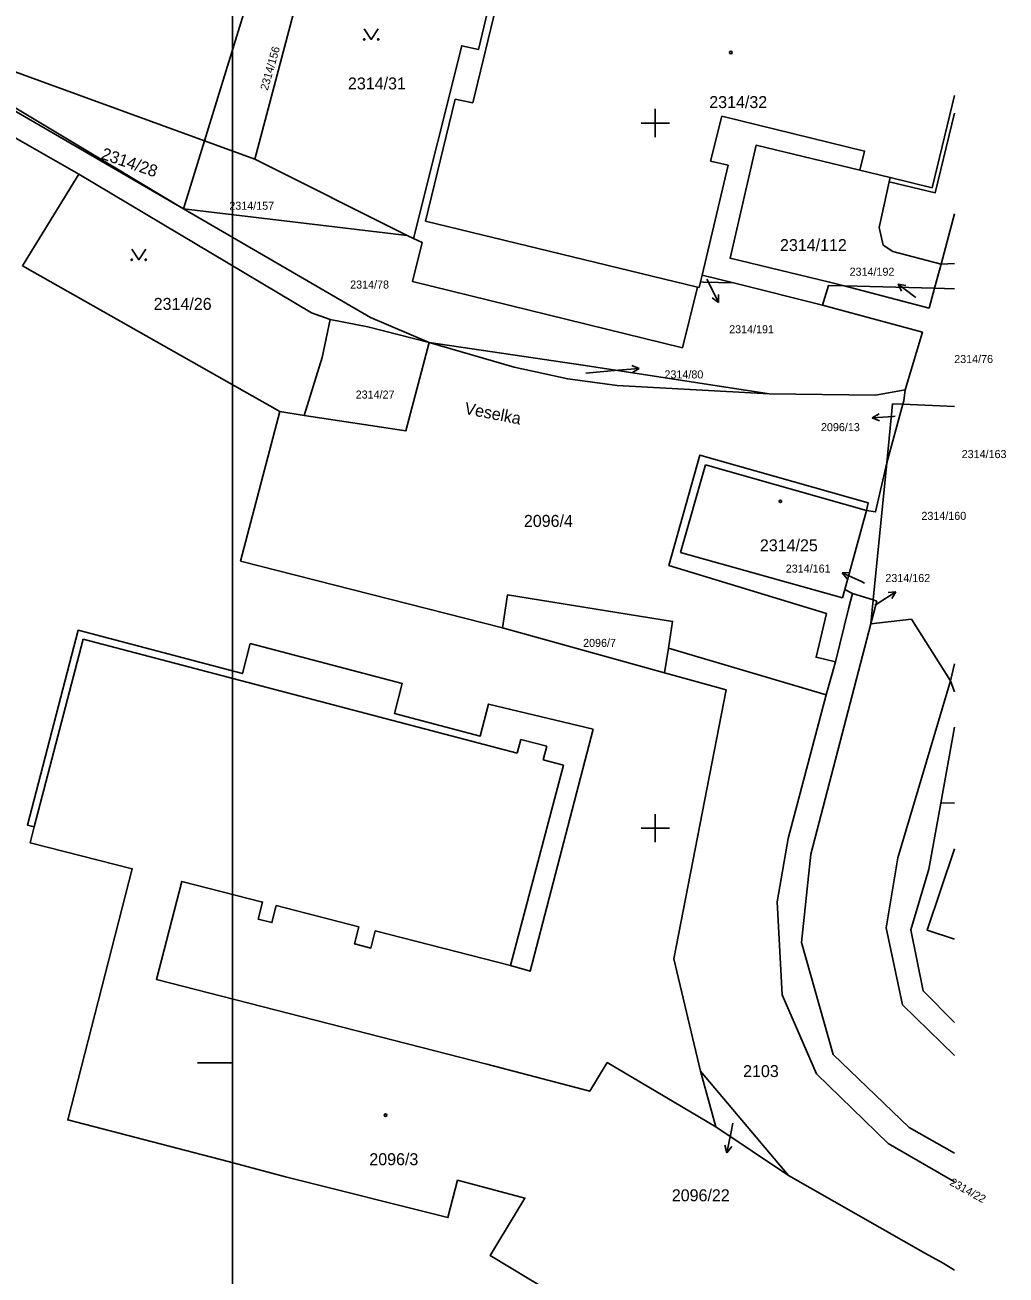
# Model space of a CAD drawing. Extents: x -599970 to -599524, y -1154772 to -1154457.
# Drawn here: x -599594.7 to -599525.1, y -1154681.7 to -1154593 of the extents above; entities that cross this region are included whole.
import ezdxf

# ---------------------------------------------------------------- set-up
doc = ezdxf.new("R2010")
doc.units = 0
for name, color, linetype in [('Z-KATASTRALNI MAPA', 7, 'Continuous'), ('Z-KRIZKY CTVERCOVE SITE', 7, 'Continuous'), ('Z-RAM ROZPISKA', 7, 'Continuous')]:
    doc.layers.add(name, color=color, linetype=linetype)

msp = doc.modelspace()

# ---------------------------------------------------------------- linework, layer by layer
at = {"layer": 'Z-KATASTRALNI MAPA'}
for p, q in [((-599562.95, -1154598.56), (-599560.21, -1154587.23)), ((-599581.98, -1154601.27), (-599578.2, -1154588.98)), ((-599575.02, -1154589.76), (-599578.41, -1154602.57)), ((-599581.98, -1154601.27), (-599603.91, -1154593.29)), ((-599590.89, -1154603.63), (-599607.38, -1154594.23)), ((-599528.77, -1154598.05), (-599530.36, -1154604.59)), ((-599566.31, -1154606.95), (-599564.2, -1154598.31)), ((-599564.2, -1154598.31), (-599562.95, -1154598.56)), ((-599546.08, -1154602.7), (-599545.28, -1154599.52)), ((-599583.46, -1154606.09), (-599581.98, -1154601.27)), ((-599581.98, -1154601.27), (-599578.41, -1154602.57)), ((-599578.41, -1154602.57), (-599567.6, -1154607.98)), ((-599544.84, -1154602.99), (-599546.08, -1154602.7)), ((-599546.68, -1154610.8), (-599544.84, -1154602.99)), ((-599590.89, -1154603.63), (-599594.88, -1154610.13)), ((-599574.38, -1154613.45), (-599590.89, -1154603.63)), ((-599530.36, -1154604.59), (-599533.33, -1154603.87)), ((-599567.6, -1154607.98), (-599583.46, -1154606.09)), ((-599566.31, -1154606.95), (-599547.01, -1154611.63)), ((-599567.6, -1154607.98), (-599567.16, -1154608.2)), ((-599576.64, -1154620.46), (-599594.88, -1154610.13)), ((-599529.73, -1154610.01), (-599530.19, -1154611.71)), ((-599546.34, -1154611.07), (-599546.18, -1154611.38)), ((-599546.18, -1154611.38), (-599545.522, -1154612.728)), ((-599544.46, -1154611.34), (-599538.14, -1154612.91)), ((-599536.61, -1154611.55), (-599530.19, -1154611.71)), ((-599531.58, -1154612.33), (-599532.779, -1154611.427)), ((-599532.779, -1154611.427), (-599532.228, -1154611.529)), ((-599532.779, -1154611.427), (-599532.529, -1154611.928)), ((-599545.522, -1154612.728), (-599545.967, -1154612.389)), ((-599545.522, -1154612.728), (-599545.517, -1154612.169)), ((-599531.52, -1154612.38), (-599531.58, -1154612.33)), ((-599528.77, -1154611.75), (-599530.19, -1154611.71)), ((-599573.07, -1154613.94), (-599574.38, -1154613.45)), ((-599554.92, -1154617.74), (-599552.63, -1154617.53)), ((-599552.63, -1154617.53), (-599551.135, -1154617.399)), ((-599551.135, -1154617.399), (-599551.656, -1154617.194)), ((-599551.135, -1154617.399), (-599551.612, -1154617.693)), ((-599532.37, -1154619.69), (-599532.27, -1154618.91)), ((-599574.9, -1154620.73), (-599576.64, -1154620.46)), ((-599533.58, -1154624.09), (-599533.17, -1154619.91)), ((-599533.58, -1154624.09), (-599532.44, -1154619.94)), ((-599533.17, -1154619.91), (-599532.44, -1154619.94)), ((-599532.44, -1154619.94), (-599532.37, -1154619.69)), ((-599532.44, -1154619.94), (-599528.77, -1154620.09)), ((-599534.607, -1154620.904), (-599534.125, -1154620.62)), ((-599533.11, -1154620.8), (-599534.607, -1154620.904)), ((-599534.607, -1154620.904), (-599534.09, -1154621.12)), ((-599532.99, -1154620.79), (-599533.11, -1154620.8)), ((-599546.45, -1154624.24), (-599548.21, -1154630.46)), ((-599535.03, -1154627.47), (-599546.45, -1154624.24)), ((-599533.58, -1154624.09), (-599534.55, -1154633.82)), ((-599548.21, -1154630.46), (-599536.72, -1154633.66)), ((-599536.74, -1154631.886), (-599536.181, -1154631.87)), ((-599535.38, -1154632.52), (-599536.74, -1154631.886)), ((-599536.74, -1154631.886), (-599536.392, -1154632.325)), ((-599535.17, -1154632.62), (-599535.38, -1154632.52)), ((-599536.56, -1154633.08), (-599536.72, -1154633.66)), ((-599534.55, -1154633.82), (-599536, -1154633.37)), ((-599534.19, -1154634.05), (-599532.932, -1154633.233)), ((-599532.932, -1154633.233), (-599533.488, -1154633.296)), ((-599532.932, -1154633.233), (-599533.215, -1154633.715)), ((-599534.72, -1154635.51), (-599534.55, -1154633.82)), ((-599534.28, -1154633.91), (-599534.72, -1154635.51)), ((-599534.55, -1154633.82), (-599534.28, -1154633.91)), ((-599534.43, -1154634.21), (-599534.19, -1154634.05)), ((-599549.35, -1154638.99), (-599560.85, -1154635.79)), ((-599594.06, -1154649.91), (-599590.58, -1154636.59)), ((-599590.58, -1154636.59), (-599559.79, -1154644.68)), ((-599549.07, -1154637.23), (-599549.35, -1154638.99)), ((-599549.07, -1154637.23), (-599537.89, -1154640.54)), ((-599537.89, -1154640.54), (-599537.21, -1154638.21)), ((-599529.06, -1154639.56), (-599528.77, -1154638.35)), ((-599528.77, -1154640.34), (-599529.06, -1154639.56)), ((-599528.77, -1154642.85), (-599529.74, -1154648.23)), ((-599559.79, -1154644.68), (-599559.53, -1154643.71)), ((-599559.53, -1154643.71), (-599557.7, -1154644.19)), ((-599557.7, -1154644.19), (-599557.95, -1154645.16)), ((-599557.95, -1154645.16), (-599556.5, -1154645.54)), ((-599556.5, -1154645.54), (-599560.26, -1154659.74)), ((-599529.74, -1154648.23), (-599530.59, -1154652.91)), ((-599546.79, -1154667.23), (-599540.54, -1154674.64)), ((-599545.71, -1154671.17), (-599546.79, -1154667.23)), ((-599544.51, -1154670.93), (-599544.63, -1154671.54)), ((-599540.54, -1154674.64), (-599545.71, -1154671.17)), ((-599544.63, -1154671.54), (-599544.917, -1154673.013)), ((-599544.917, -1154673.013), (-599545.066, -1154672.474)), ((-599544.917, -1154673.013), (-599544.575, -1154672.569))]:
    msp.add_line(p, q, dxfattribs=at)
for points in [[(-599583.46, -1154606.09), (-599606.05, -1154592.99), (-599616.82, -1154586.68), (-599619.77, -1154584.89)], [(-599567.16, -1154608.2), (-599563.73, -1154594.52), (-599562.55, -1154594.79), (-599561.88, -1154592.02), (-599562.89, -1154591.75), (-599561.93, -1154587.23)], [(-599603.91, -1154593.29), (-599600.41, -1154595.91), (-599583.46, -1154606.09)], [(-599570.65, -1154593.319), (-599570.15, -1154594.07), (-599569.65, -1154593.319)], [(-599545.28, -1154599.52), (-599535.15, -1154601.99), (-599535.48, -1154603.35)], [(-599533.4, -1154604.16), (-599530.14, -1154604.95), (-599528.77, -1154599.31)], [(-599536.61, -1154611.55), (-599537.64, -1154611.28), (-599544.7, -1154609.59), (-599542.85, -1154601.58), (-599535.48, -1154603.35), (-599533.33, -1154603.87), (-599533.4, -1154604.16)], [(-599533.4, -1154604.16), (-599534.13, -1154607.41), (-599533.83, -1154608.66), (-599533.15, -1154609.11), (-599529.73, -1154610.01)], [(-599566.04, -1154615.56), (-599570.21, -1154613.78), (-599583.46, -1154606.09)], [(-599529.73, -1154610.01), (-599528.77, -1154606.44)], [(-599567.16, -1154608.2), (-599566.53, -1154608.48), (-599567.23, -1154611.23), (-599548.08, -1154615.94), (-599547.01, -1154611.63), (-599546.89, -1154611.66), (-599546.79, -1154611.26)], [(-599587.14, -1154608.95), (-599586.64, -1154609.7), (-599586.14, -1154608.95)], [(-599528.77, -1154609.96), (-599529.73, -1154610.01)], [(-599546.79, -1154611.26), (-599546.68, -1154610.8), (-599544.46, -1154611.34)], [(-599544.46, -1154611.34), (-599546.57, -1154611.29), (-599546.79, -1154611.26)], [(-599536.61, -1154611.55), (-599537.71, -1154611.52), (-599538.14, -1154612.91)], [(-599530.19, -1154611.71), (-599530.58, -1154613.12), (-599536.61, -1154611.55)], [(-599538.14, -1154612.91), (-599531.05, -1154614.84), (-599532.27, -1154618.91)], [(-599574.9, -1154620.73), (-599573.64, -1154616.63), (-599573.07, -1154613.94)], [(-599573.07, -1154613.94), (-599570.39, -1154614.46), (-599566.04, -1154615.56)], [(-599566.04, -1154615.56), (-599567.7, -1154621.83), (-599574.9, -1154620.73)], [(-599566.04, -1154615.56), (-599554.97, -1154617.19), (-599541.92, -1154619.2)], [(-599541.92, -1154619.2), (-599552.71, -1154618.61), (-599556.21, -1154618.14), (-599560.02, -1154617.32), (-599566.04, -1154615.56)], [(-599532.27, -1154618.91), (-599534.38, -1154619.29), (-599541.92, -1154619.2)], [(-599560.85, -1154635.79), (-599579.42, -1154631.08), (-599576.64, -1154620.46)], [(-599537.21, -1154638.21), (-599538.59, -1154637.88), (-599537.86, -1154634.79), (-599549.03, -1154631.37), (-599546.84, -1154623.55), (-599534.89, -1154626.94), (-599535.03, -1154627.47)], [(-599535.03, -1154627.47), (-599534.37, -1154627.58), (-599533.58, -1154624.09)], [(-599535.03, -1154627.47), (-599536.56, -1154633.08), (-599536, -1154633.37)], [(-599560.85, -1154635.79), (-599560.48, -1154633.45), (-599548.77, -1154635.34), (-599549.07, -1154637.23)], [(-599536, -1154633.37), (-599536.29, -1154634.44), (-599537.21, -1154638.21)], [(-599528.77, -1154673.04), (-599531.99, -1154671.23), (-599537.38, -1154666.05), (-599539.64, -1154658.11), (-599538.96, -1154651.84), (-599534.72, -1154635.51)], [(-599529.06, -1154639.56), (-599531.83, -1154635.19), (-599534.72, -1154635.51)], [(-599538.86, -1154724.66), (-599552.58, -1154716.5), (-599539.08, -1154693.79), (-599548.26, -1154688.39), (-599554.98, -1154684.38), (-599561.71, -1154680.31), (-599559.25, -1154676.23), (-599564.02, -1154674.97), (-599564.71, -1154677.61), (-599576.23, -1154674.72), (-599580.3, -1154673.63), (-599591.68, -1154670.69), (-599587.1, -1154652.88), (-599594.35, -1154651.03), (-599594.06, -1154649.91), (-599594.54, -1154649.78), (-599590.94, -1154635.97), (-599579.29, -1154639.04), (-599578.73, -1154636.91), (-599567.95, -1154639.74), (-599568.51, -1154641.87), (-599562.42, -1154643.47), (-599561.82, -1154641.2), (-599554.41, -1154642.98)], [(-599546.79, -1154667.23), (-599548.69, -1154659.26), (-599544.98, -1154640.2), (-599549.35, -1154638.99)], [(-599528.77, -1154666.13), (-599532.46, -1154662.52), (-599533.62, -1154657.08), (-599532.79, -1154652.11), (-599529.06, -1154639.56)], [(-599528.77, -1154675.08), (-599533.48, -1154672.35), (-599538.56, -1154667.41), (-599541, -1154661.83), (-599541.36, -1154655.23), (-599540.57, -1154650.74), (-599537.89, -1154640.54)], [(-599554.41, -1154642.98), (-599558.88, -1154660.15), (-599560.26, -1154659.74)], [(-599528.77, -1154648.21), (-599529.74, -1154648.23)], [(-599528.77, -1154657.88), (-599530.71, -1154657.24), (-599528.77, -1154651.47)], [(-599530.59, -1154652.91), (-599531.88, -1154657.21), (-599531, -1154661.54), (-599528.77, -1154663.78)], [(-599560.26, -1154659.74), (-599569.86, -1154657.29), (-599570.17, -1154658.5), (-599571.34, -1154658.2), (-599571.03, -1154656.99), (-599576.89, -1154655.49), (-599577.2, -1154656.7), (-599578.17, -1154656.45), (-599577.86, -1154655.24), (-599583.59, -1154653.78), (-599585.39, -1154660.73), (-599561.95, -1154666.73), (-599554.65, -1154668.66), (-599553.41, -1154666.62), (-599545.71, -1154671.17)], [(-599528.77, -1154681.34), (-599529.59, -1154680.84), (-599530.84, -1154680.16), (-599540.54, -1154674.64)]]:
    msp.add_lwpolyline(points, dxfattribs=at)
for centre, radius in [((-599570.65, -1154594.07), 0.05), ((-599569.65, -1154594.07), 0.05), ((-599544.643, -1154595), 0.0875), ((-599587.14, -1154609.7), 0.05), ((-599586.14, -1154609.7), 0.05), ((-599541.123, -1154626.82), 0.0875), ((-599569.133, -1154670.35), 0.0875)]:
    msp.add_circle(centre, radius, dxfattribs=at)
at = {"layer": 'Z-KRIZKY CTVERCOVE SITE'}
for p, q in [((-599550, -1154601), (-599550, -1154599)), ((-599549, -1154600), (-599551, -1154600)), ((-599550, -1154651), (-599550, -1154649)), ((-599549, -1154650), (-599551, -1154650))]:
    msp.add_line(p, q, dxfattribs=at)
at = {"layer": 'Z-RAM ROZPISKA'}
msp.add_line((-599579.98, -1154666.65), (-599582.48, -1154666.65), dxfattribs=at)
msp.add_lwpolyline([(-599876.98, -1154456.65), (-599579.98, -1154456.65), (-599579.98, -1154771.65), (-599876.98, -1154771.65)], close=True, dxfattribs=at)

# ---------------------------------------------------------------- texts
at = {"layer": 'Z-KATASTRALNI MAPA'}
for s, height, rotation, p in [('2314/156', 0.57, 74, (-599577.493, -1154597.726)), ('2314/28', 0.85, 341, (-599589.371, -1154602.522)), ('Veselka', 0.85, 349, (-599563.584, -1154620.617)), ('2314/22', 0.57, 331, (-599529.169, -1154675.274))]:
    msp.add_text(s, height=height, rotation=rotation, dxfattribs=at).set_placement(p)
for s, height, p in [('2314/31', 0.85, (-599571.802, -1154597.62)), ('2314/32', 0.85, (-599546.173, -1154598.94)), ('2314/157', 0.57, (-599580.217, -1154606.15)), ('2314/112', 0.85, (-599541.156, -1154609.08)), ('2314/192', 0.57, (-599536.219, -1154610.83)), ('2314/78', 0.57, (-599571.644, -1154611.74)), ('2314/26', 0.85, (-599585.579, -1154613.25)), ('2314/191', 0.57, (-599544.76, -1154614.91)), ('2314/76', 0.57, (-599528.797, -1154617.02)), ('2314/80', 0.57, (-599549.35, -1154618.11)), ('2314/27', 0.57, (-599571.252, -1154619.54)), ('2096/13', 0.57, (-599538.249, -1154621.85)), ('2314/163', 0.57, (-599528.268, -1154623.76)), ('2314/160', 0.57, (-599531.124, -1154628.14)), ('2096/4', 0.85, (-599559.321, -1154628.64)), ('2314/25', 0.85, (-599542.582, -1154630.37)), ('2314/161', 0.57, (-599540.747, -1154631.88)), ('2314/162', 0.57, (-599533.68, -1154632.55)), ('2096/7', 0.57, (-599555.122, -1154637.15)), ('2103', 0.85, (-599543.771, -1154667.65)), ('2096/3', 0.85, (-599570.285, -1154673.9)), ('2096/22', 0.85, (-599548.829, -1154676.46))]:
    msp.add_text(s, height=height, dxfattribs=at).set_placement(p)

doc.saveas('drawing.dxf')
